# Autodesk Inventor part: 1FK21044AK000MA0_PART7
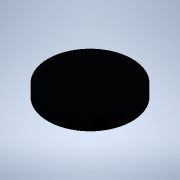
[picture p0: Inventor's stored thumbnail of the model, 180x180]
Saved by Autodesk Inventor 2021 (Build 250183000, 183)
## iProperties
Created: 2025-04
Part Number: 1FK21044AK000MA0_PART7
Material: Generic
Catalog Web Link: www.3dfindit.com
Description: -Servo synchronous motor
Document SubType Name: Modeling
Designer: psAdmin
Mass: 0.299142 g
Surface Area: 3.8585 cm^2
Volume: 0.299142 cm^3
Density: 1 g/cm^3
Appearance: PSOLRGB-38-46-56
Category: PARTsolutions
Title: 1FK21044AK000MA0_PART7
Author: Cadenas PARTsolutions
Comments: Servo synchronous motor
Sending System: PARTsolutions
Preprocessor: ST-DEVELOPER v19.3
PSOL_IDENT_0: {$CADENAS_DATA/23d-libs/siemens_ag/_cat_/87/f4/1fk21044ak000ma0.prj},213 {VTYP=3D},{NB=1FK21044AK000
PSOL_IDENT_1: MA0_PART7},{LINA=1FK21044AK000MA0_PART7},{NN=1FK21044AK000MA0_PART7},{NOPRJ=TRUE},{DATE=19.08.2025 1
PSOL_IDENT_2: 4:00:48},{GEOMDATE=30.07.2025 02:00:50},{VERSION=},{LINEID=10},{WBVAR=},{WBNUMERIC=}  {NB=1FK21044AK
PSOL_IDENT_3: 000MA0_PART7},{LINA=1FK21044AK000MA0_PART7},{KT=DUMMY},{PREVIEW=../../../_pool_/cb/72/p_d211_xx_0043
PSOL_IDENT_4: 4j.png},{DESCSHORT=SIMOTICS S-1FK2 HD, SINAMICS S210 3AC 400V-480V, 0.95 Nm, 6000 rpm},{DESCLONG=SIM
PSOL_IDENT_5: OTICS S-1FK2 HD servo motor M0=1.27 Nm; PN = 0.6 kW at nN=6000 rpm (380-480 V); PN = 0.4 kW at nN=30
PSOL_IDENT_6: 00 rpm (200-240 V); degree of protection IP64; cylindrical shaft D19x40mm; absolute encoder 22-bit +
PSOL_IDENT_7: 12-bit multiturn (encoder AM22DQC); with OCC interface; plug size M17, rotatable; SIMOTICS S-1FK2 s
PSOL_IDENT_8: ervomotorfor a wide range of uses in industrial environments. SIMOTICS S‑1FK2 servomotors are compac
PSOL_IDENT_9: t synchronous motors with a high dynamic performance that set themselves apart as a result of their
PSOL_IDENT_10: high power density, degree of protection and overload capability. The motors are available in two va
PSOL_IDENT_11: riants: as High Dynamic variant (highest dynamic performance as a result of the low intrinsic moment
PSOL_IDENT_12: of inertia for applications demanding a high dynamic performance with low moved masses) - and as Co
PSOL_IDENT_13: mpact variant (precise and stable closed-loop control for medium up to large moved masses as a resul
PSOL_IDENT_14: t of a medium intrinsic moment of inertia). SIMOTICSS‑1FK2 servomotors fully exploit their strengths
PSOL_IDENT_15: in a system with the SINAMICSS210 frequency converter and simple connection using the one cable con
PSOL_IDENT_16: nection (OCC). Advantages include the short control and positioning times, fast and precise correcti
PSOL_IDENT_17: on of disturbing quantities as well as stable control with a high dynamic performance. The servo mot
PSOL_IDENT_18: ors can be configured to address a wide range of requirements. For example with and without holding
PSOL_IDENT_19: brake, IP64 or IP65 degree of protection, singleturn or multiturn absolute encoders - to name just a
PSOL_IDENT_20: few. Further, the servomotors are available in different shaft heights extending from 20 to 100. A
PSOL_IDENT_21: shaft sealing ring is available to achieve an IP65 degree of protection and for subsequent mounting
PSOL_IDENT_22: at the motor or as spare part. SIMOTICS - the optimum motor for each and every motion control applic
PSOL_IDENT_23: ation.},{INTNO=195125056312},{SUPPLIERALTNO=1FK2104-4AK00-0MA0},{MANUID=1FK21044AK000MA0},{MANUNAME=
PSOL_IDENT_24: Siemens},{MANUTYPEDESC=Synchronous motor 1FK2-HD 1,27 Nm},{AAU732=SIMOTICS},{AAO057=S-1FK2},{AAU734=
PSOL_IDENT_25: SIMOTICS S-1FK2 HD servo motor M0=1.27 Nm; PN = 0.6 kW at nN=6000 rpm (380-480 V); PN = 0.4 kW at nN=
PSOL_IDENT_26: 3000 rpm (200-240 V); degree of protection IP64; cylindrical shaft D19x40mm; absolute encoder 22-bit
PSOL_IDENT_27: + 12-bit multiturn (encoder AM22DQC); with OCC interface; plug size M17, rotatable;},{AAW338=Synchr
PSOL_IDENT_28: onous motor 1FK2-HD 1,27 Nm},{AAO742=SIMOTICS},{AAO663=4042948690994},{NOCUPEROU=1},{PRICEQUANTITY=1
PSOL_IDENT_29: },{QUANTITYMIN=1},{QUANTITYINT=1},{CTN=85015100},{COO=DE},{AAO676=1FK2104-4AK00-0MA0},{AAO677=Siemen
PSOL_IDENT_30: s AG},{ORDERUNIT=C62},{CONTENTUNIT=C62}
NB: 1FK21044AK000MA0_PART7
NT: Servo synchronous motor
NBSYN: $MANUID._PART7
LINA: 1FK21044AK000MA0_PART7
CATALOG: SIEMENS
PREVIEW: ../../../_pool_/cb/72/p_d211_xx_00434j.png
DESCSHORT: SIMOTICS S-1FK2 HD, SINAMICS S210 3AC 400V-480V, 0.95 Nm, 6000 rpm
DESCLONG: SIMOTICS S-1FK2 HD servo motor M0=1.27 Nm; PN = 0.6 kW at nN=6000 rpm (380-480 V); PN = 0.4 kW at nN=3000 rpm (200-240 V); degree of protection IP64; cylindrica
INTNO: 195125056312
SUPPLIERALTNO: 1FK2104-4AK00-0MA0
MANUID: 1FK21044AK000MA0
MANUNAME: Siemens
MANUTYPEDESC: Synchronous motor 1FK2-HD 1,27 Nm
AAU732: SIMOTICS
AAO057: S-1FK2
AAU734: SIMOTICS S-1FK2 HD servo motor M0=1.27 Nm; PN = 0.6 kW at nN=6000 rpm (380-480 V); PN = 0.4 kW at nN=3000 rpm (200-240 V); degree of protection IP64; cylindrica
AAW338: Synchronous motor 1FK2-HD 1,27 Nm
AAO742: SIMOTICS
AAO663: 4042948690994.0
NOCUPEROU: 1
PRICEQUANTITY: 1
QUANTITYMIN: 1
QUANTITYINT: 1
CTN: 85015100
COO: DE
ARTICLENO: 1FK21044AK000MA0_PART7
BOMINFO: 1FK21044AK000MA0_PART7
CREATOR: CADENAS GmbH
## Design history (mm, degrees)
feature "2025_04_17_15_37_40_0556"
body "Solid1"
